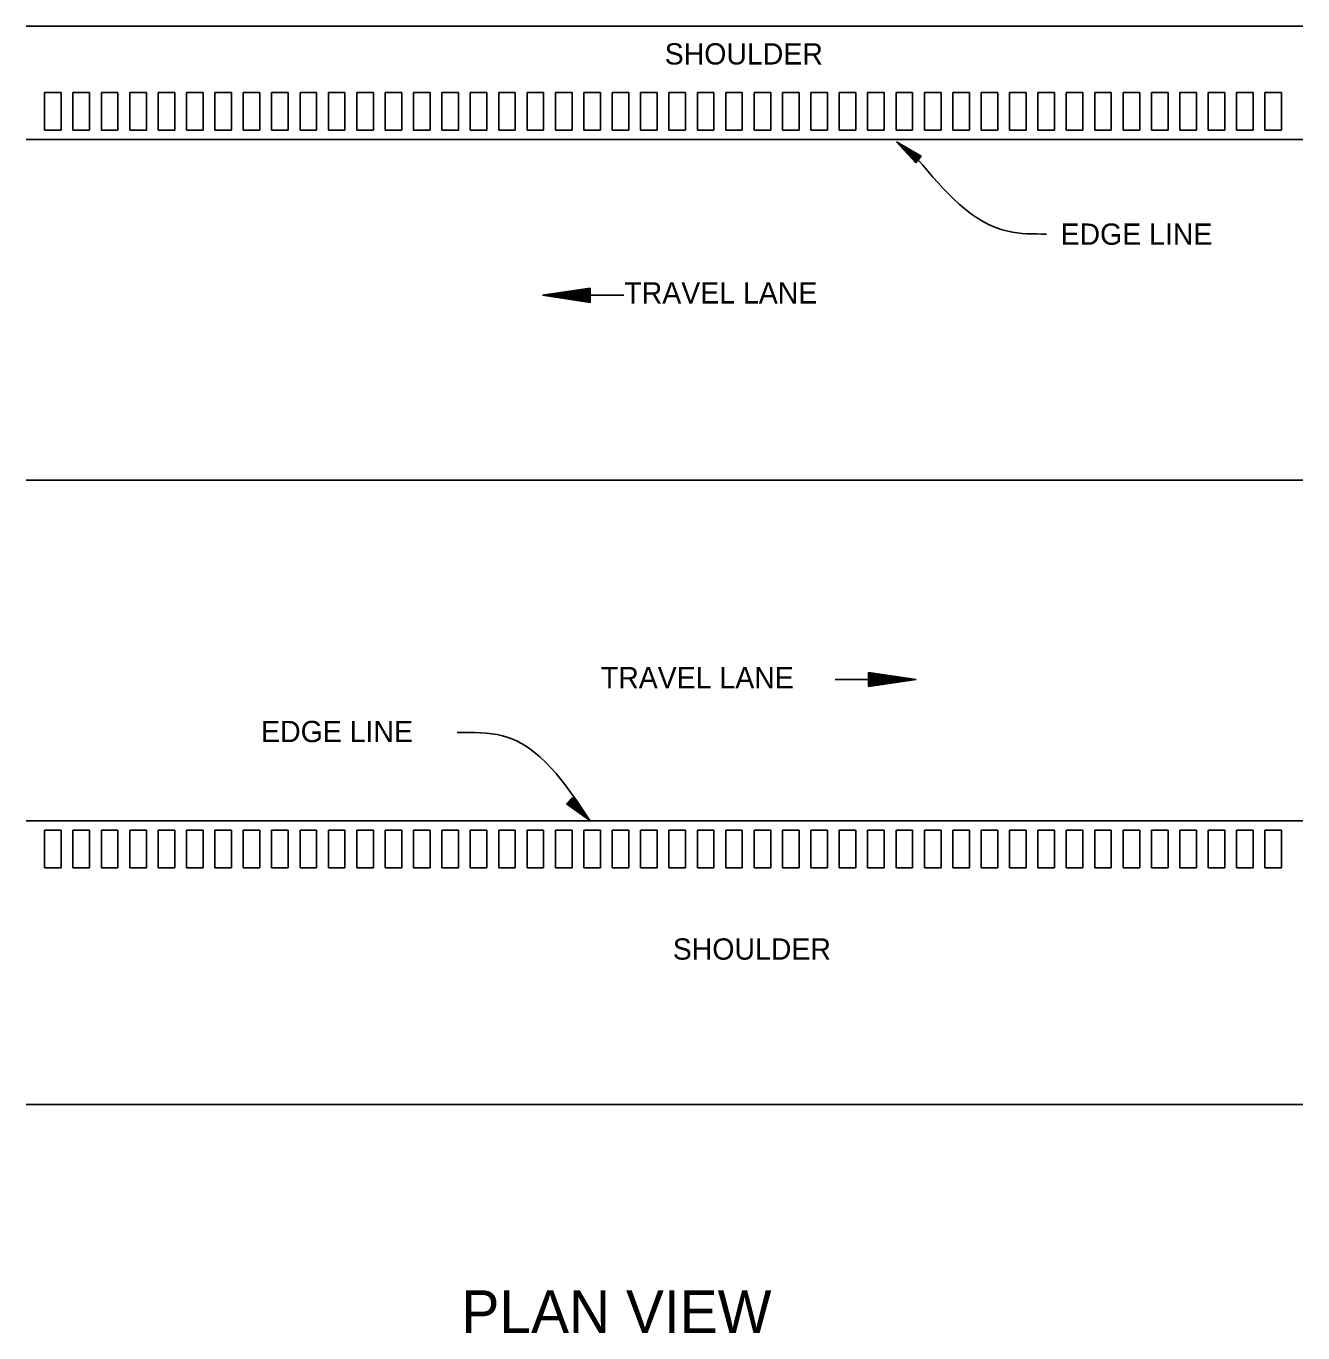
# Model space of a CAD drawing. Extents: x -2842 to 2681, y -2139 to 474.
# Drawn here: x -712.1 to -352.2, y -354.1 to 14.3 of the extents above; entities that cross this region are included whole.
import ezdxf

# ---------------------------------------------------------------- set-up
doc = ezdxf.new("R2010")
doc.units = 0
doc.layers.add('Default', color=7, linetype='Continuous')

msp = doc.modelspace()

# ---------------------------------------------------------------- linework, layer by layer
at = {"layer": 'Default'}
for p, q in [((-712.07, 14.26), (-352.18, 14.26)), ((-706.87, -15.08), (-706.87, -4.44)), ((-706.87, -4.44), (-702.19, -4.44)), ((-702.19, -15.08), (-702.19, -4.44)), ((-698.87, -15.08), (-698.87, -4.44)), ((-698.87, -4.44), (-694.19, -4.44)), ((-694.19, -15.08), (-694.19, -4.44)), ((-690.87, -15.08), (-690.87, -4.44)), ((-690.87, -4.44), (-686.19, -4.44)), ((-686.19, -15.08), (-686.19, -4.44)), ((-682.87, -15.08), (-682.87, -4.44)), ((-682.87, -4.44), (-678.19, -4.44)), ((-678.19, -15.08), (-678.19, -4.44)), ((-674.87, -15.08), (-674.87, -4.44)), ((-674.87, -4.44), (-670.19, -4.44)), ((-670.19, -15.08), (-670.19, -4.44)), ((-666.87, -15.08), (-666.87, -4.44)), ((-666.87, -4.44), (-662.19, -4.44)), ((-662.19, -15.08), (-662.19, -4.44)), ((-658.87, -15.08), (-658.87, -4.44)), ((-658.87, -4.44), (-654.19, -4.44)), ((-654.19, -15.08), (-654.19, -4.44)), ((-650.87, -15.08), (-650.87, -4.44)), ((-650.87, -4.44), (-646.19, -4.44)), ((-646.19, -15.08), (-646.19, -4.44)), ((-642.87, -15.08), (-642.87, -4.44)), ((-642.87, -4.44), (-638.19, -4.44)), ((-638.19, -15.08), (-638.19, -4.44)), ((-634.87, -15.08), (-634.87, -4.44)), ((-634.87, -4.44), (-630.19, -4.44)), ((-630.19, -15.08), (-630.19, -4.44)), ((-626.87, -15.08), (-626.87, -4.44)), ((-626.87, -4.44), (-622.19, -4.44)), ((-622.19, -15.08), (-622.19, -4.44)), ((-618.87, -15.08), (-618.87, -4.44)), ((-618.87, -4.44), (-614.19, -4.44)), ((-614.19, -15.08), (-614.19, -4.44)), ((-610.87, -15.08), (-610.87, -4.44)), ((-610.87, -4.44), (-606.19, -4.44)), ((-606.19, -15.08), (-606.19, -4.44)), ((-602.87, -15.08), (-602.87, -4.44)), ((-602.87, -4.44), (-598.19, -4.44)), ((-598.19, -15.08), (-598.19, -4.44)), ((-594.87, -15.08), (-594.87, -4.44)), ((-594.87, -4.44), (-590.19, -4.44)), ((-590.19, -15.08), (-590.19, -4.44)), ((-586.87, -15.08), (-586.87, -4.44)), ((-586.87, -15.08), (-586.87, -4.44)), ((-586.87, -4.44), (-582.19, -4.44)), ((-582.19, -15.08), (-582.19, -4.44)), ((-578.87, -15.08), (-578.87, -4.44)), ((-578.87, -4.44), (-574.19, -4.44)), ((-574.19, -15.08), (-574.19, -4.44)), ((-570.87, -15.08), (-570.87, -4.44)), ((-570.87, -4.44), (-566.19, -4.44)), ((-566.19, -15.08), (-566.19, -4.44)), ((-562.87, -15.08), (-562.87, -4.44)), ((-562.87, -4.44), (-558.19, -4.44)), ((-558.19, -15.08), (-558.19, -4.44)), ((-554.87, -15.08), (-554.87, -4.44)), ((-554.87, -4.44), (-550.19, -4.44)), ((-550.19, -15.08), (-550.19, -4.44)), ((-546.87, -15.08), (-546.87, -4.44)), ((-546.87, -4.44), (-542.19, -4.44)), ((-542.19, -15.08), (-542.19, -4.44)), ((-538.87, -15.08), (-538.87, -4.44)), ((-538.87, -4.44), (-534.19, -4.44)), ((-534.19, -15.08), (-534.19, -4.44)), ((-530.87, -15.08), (-530.87, -4.44)), ((-530.87, -4.44), (-526.19, -4.44)), ((-526.19, -15.08), (-526.19, -4.44)), ((-522.87, -15.08), (-522.87, -4.44)), ((-522.87, -4.44), (-518.19, -4.44)), ((-518.19, -15.08), (-518.19, -4.44)), ((-514.87, -15.08), (-514.87, -4.44)), ((-514.87, -4.44), (-510.19, -4.44)), ((-510.19, -15.08), (-510.19, -4.44)), ((-506.87, -15.08), (-506.87, -4.44)), ((-506.87, -4.44), (-502.19, -4.44)), ((-502.19, -15.08), (-502.19, -4.44)), ((-498.87, -15.08), (-498.87, -4.44)), ((-498.87, -4.44), (-494.19, -4.44)), ((-494.19, -15.08), (-494.19, -4.44)), ((-490.87, -15.08), (-490.87, -4.44)), ((-490.87, -4.44), (-486.19, -4.44)), ((-486.19, -15.08), (-486.19, -4.44)), ((-482.87, -15.08), (-482.87, -4.44)), ((-482.87, -4.44), (-478.18, -4.44)), ((-478.18, -15.08), (-478.18, -4.44)), ((-474.86, -15.08), (-474.86, -4.44)), ((-474.86, -4.44), (-470.18, -4.44)), ((-470.18, -15.08), (-470.18, -4.44)), ((-466.86, -15.08), (-466.86, -4.44)), ((-466.86, -4.44), (-462.18, -4.44)), ((-462.18, -15.08), (-462.18, -4.44)), ((-458.86, -15.08), (-458.86, -4.44)), ((-458.86, -4.44), (-454.18, -4.44)), ((-454.18, -15.08), (-454.18, -4.44)), ((-450.86, -15.08), (-450.86, -4.44)), ((-450.86, -4.44), (-446.18, -4.44)), ((-446.18, -15.08), (-446.18, -4.44)), ((-442.86, -15.08), (-442.86, -4.44)), ((-442.86, -4.44), (-438.18, -4.44)), ((-438.18, -15.08), (-438.18, -4.44)), ((-434.86, -15.08), (-434.86, -4.44)), ((-434.86, -4.44), (-430.18, -4.44)), ((-430.18, -15.08), (-430.18, -4.44)), ((-426.86, -15.08), (-426.86, -4.44)), ((-426.86, -4.44), (-422.18, -4.44)), ((-422.18, -15.08), (-422.18, -4.44)), ((-418.86, -15.08), (-418.86, -4.44)), ((-418.86, -4.44), (-414.18, -4.44)), ((-414.18, -15.08), (-414.18, -4.44)), ((-410.86, -15.08), (-410.86, -4.44)), ((-410.86, -4.44), (-406.18, -4.44)), ((-406.18, -15.08), (-406.18, -4.44)), ((-402.86, -15.08), (-402.86, -4.44)), ((-402.86, -4.44), (-398.18, -4.44)), ((-398.18, -15.08), (-398.18, -4.44)), ((-394.86, -15.08), (-394.86, -4.44)), ((-394.86, -4.44), (-390.18, -4.44)), ((-390.18, -15.08), (-390.18, -4.44)), ((-386.86, -15.08), (-386.86, -4.44)), ((-386.86, -4.44), (-382.18, -4.44)), ((-382.18, -15.08), (-382.18, -4.44)), ((-378.86, -15.08), (-378.86, -4.44)), ((-378.86, -4.44), (-374.18, -4.44)), ((-374.18, -15.08), (-374.18, -4.44)), ((-370.86, -15.08), (-370.86, -4.44)), ((-370.86, -4.44), (-366.18, -4.44)), ((-366.18, -15.08), (-366.18, -4.44)), ((-362.86, -15.08), (-362.86, -4.44)), ((-362.86, -4.44), (-358.18, -4.44)), ((-358.18, -15.08), (-358.18, -4.44)), ((-712.07, -17.74), (-532.97, -17.74)), ((-702.19, -15.08), (-706.87, -15.08)), ((-694.19, -15.08), (-698.87, -15.08)), ((-686.19, -15.08), (-690.87, -15.08)), ((-678.19, -15.08), (-682.87, -15.08)), ((-670.19, -15.08), (-674.87, -15.08)), ((-662.19, -15.08), (-666.87, -15.08)), ((-654.19, -15.08), (-658.87, -15.08)), ((-646.19, -15.08), (-650.87, -15.08)), ((-638.19, -15.08), (-642.87, -15.08)), ((-630.19, -15.08), (-634.87, -15.08)), ((-622.19, -15.08), (-626.87, -15.08)), ((-614.19, -15.08), (-618.87, -15.08)), ((-606.19, -15.08), (-610.87, -15.08)), ((-598.19, -15.08), (-602.87, -15.08)), ((-590.19, -15.08), (-594.87, -15.08)), ((-582.19, -15.08), (-586.87, -15.08)), ((-574.19, -15.08), (-578.87, -15.08)), ((-566.19, -15.08), (-570.87, -15.08)), ((-558.19, -15.08), (-562.87, -15.08)), ((-550.19, -15.08), (-554.87, -15.08)), ((-542.19, -15.08), (-546.87, -15.08)), ((-534.19, -15.08), (-538.87, -15.08)), ((-352.18, -17.74), (-532.97, -17.74)), ((-526.19, -15.08), (-530.87, -15.08)), ((-518.19, -15.08), (-522.87, -15.08)), ((-510.19, -15.08), (-514.87, -15.08)), ((-502.19, -15.08), (-506.87, -15.08)), ((-494.19, -15.08), (-498.87, -15.08)), ((-486.19, -15.08), (-490.87, -15.08)), ((-478.18, -15.08), (-482.87, -15.08)), ((-470.18, -15.08), (-474.86, -15.08)), ((-462.18, -15.08), (-466.86, -15.08)), ((-461.24, -24.3), (-466.74, -18.36)), ((-459.74, -22.42), (-466.74, -18.36)), ((-454.18, -15.08), (-458.86, -15.08)), ((-446.18, -15.08), (-450.86, -15.08)), ((-438.18, -15.08), (-442.86, -15.08)), ((-430.18, -15.08), (-434.86, -15.08)), ((-422.18, -15.08), (-426.86, -15.08)), ((-414.18, -15.08), (-418.86, -15.08)), ((-406.18, -15.08), (-410.86, -15.08)), ((-398.18, -15.08), (-402.86, -15.08)), ((-390.18, -15.08), (-394.86, -15.08)), ((-382.18, -15.08), (-386.86, -15.08)), ((-374.18, -15.08), (-378.86, -15.08)), ((-366.18, -15.08), (-370.86, -15.08)), ((-358.18, -15.08), (-362.86, -15.08)), ((-461.12, -24.14), (-465.7, -19.2)), ((-459.86, -22.58), (-465.7, -19.2)), ((-460, -22.74), (-464.62, -20.04)), ((-460.98, -23.98), (-464.62, -20.04)), ((-460.86, -23.82), (-463.58, -20.88)), ((-460.12, -22.9), (-463.58, -20.88)), ((-460.26, -23.06), (-462.52, -21.74)), ((-460.74, -23.66), (-462.52, -21.74)), ((-460.38, -23.22), (-461.48, -22.56)), ((-460.62, -23.5), (-461.48, -22.56)), ((-461.24, -24.3), (-459.74, -22.42)), ((-553.05, -59.6), (-566.49, -61.62)), ((-543.61, -61.62), (-566.49, -61.62)), ((-553.05, -63.62), (-566.49, -61.62)), ((-553.05, -59.94), (-564.25, -61.62)), ((-553.05, -63.3), (-564.25, -61.62)), ((-553.05, -60.26), (-561.95, -61.62)), ((-553.05, -62.94), (-561.95, -61.62)), ((-553.05, -60.62), (-559.73, -61.62)), ((-553.05, -62.62), (-559.73, -61.62)), ((-553.05, -60.98), (-557.43, -61.62)), ((-553.05, -62.28), (-557.43, -61.62)), ((-553.05, -61.28), (-555.19, -61.62)), ((-553.05, -61.94), (-555.19, -61.62)), ((-553.05, -59.6), (-553.05, -63.62)), ((-712.07, -113.74), (-352.18, -113.74)), ((-474.58, -167.94), (-461.14, -169.92)), ((-474.58, -171.94), (-474.58, -167.94)), ((-474.58, -168.26), (-463.38, -169.92)), ((-474.58, -168.6), (-465.68, -169.92)), ((-474.58, -168.94), (-467.9, -169.92)), ((-474.58, -169.28), (-470.2, -169.92)), ((-484.03, -169.92), (-461.14, -169.92)), ((-474.58, -169.6), (-472.44, -169.92)), ((-474.58, -171.94), (-461.14, -169.92)), ((-474.58, -170.58), (-470.2, -169.92)), ((-474.58, -171.28), (-465.68, -169.92)), ((-474.58, -171.62), (-463.38, -169.92)), ((-474.58, -170.94), (-467.9, -169.92)), ((-474.58, -170.26), (-472.44, -169.92)), ((-558.07, -203.25), (-559.73, -204.97)), ((-559.73, -204.97), (-553.15, -209.69)), ((-559.59, -204.83), (-554.11, -208.75)), ((-559.45, -204.69), (-555.11, -207.79)), ((-559.31, -204.55), (-556.05, -206.87)), ((-559.17, -204.41), (-557.03, -205.93)), ((-559.03, -204.25), (-557.99, -204.99)), ((-558.77, -203.99), (-557.99, -204.99)), ((-558.63, -203.85), (-557.03, -205.93)), ((-558.49, -203.69), (-556.05, -206.87)), ((-558.35, -203.55), (-555.11, -207.79)), ((-558.21, -203.41), (-554.11, -208.75)), ((-558.07, -203.25), (-553.15, -209.69)), ((-712.07, -209.75), (-532.97, -209.75)), ((-352.18, -209.75), (-532.97, -209.75)), ((-440.06, -209.75), (-352.18, -209.75)), ((-702.19, -212.41), (-706.87, -212.41)), ((-706.87, -212.41), (-706.87, -223.05)), ((-702.19, -212.41), (-702.19, -223.05)), ((-694.19, -212.41), (-698.87, -212.41)), ((-698.87, -212.41), (-698.87, -223.05)), ((-694.19, -212.41), (-694.19, -223.05)), ((-686.19, -212.41), (-690.87, -212.41)), ((-690.87, -212.41), (-690.87, -223.05)), ((-686.19, -212.41), (-686.19, -223.05)), ((-678.19, -212.41), (-682.87, -212.41)), ((-682.87, -212.41), (-682.87, -223.05)), ((-678.19, -212.41), (-678.19, -223.05)), ((-670.19, -212.41), (-674.87, -212.41)), ((-674.87, -212.41), (-674.87, -223.05)), ((-670.19, -212.41), (-670.19, -223.05)), ((-662.19, -212.41), (-666.87, -212.41)), ((-666.87, -212.41), (-666.87, -223.05)), ((-662.19, -212.41), (-662.19, -223.05)), ((-654.19, -212.41), (-658.87, -212.41)), ((-658.87, -212.41), (-658.87, -223.05)), ((-654.19, -212.41), (-654.19, -223.05)), ((-646.19, -212.41), (-650.87, -212.41)), ((-650.87, -212.41), (-650.87, -223.05)), ((-646.19, -212.41), (-646.19, -223.05)), ((-638.19, -212.41), (-642.87, -212.41)), ((-642.87, -212.41), (-642.87, -223.05)), ((-638.19, -212.41), (-638.19, -223.05)), ((-630.19, -212.41), (-634.87, -212.41)), ((-634.87, -212.41), (-634.87, -223.05)), ((-630.19, -212.41), (-630.19, -223.05)), ((-622.19, -212.41), (-626.87, -212.41)), ((-626.87, -212.41), (-626.87, -223.05)), ((-622.19, -212.41), (-622.19, -223.05)), ((-614.19, -212.41), (-618.87, -212.41)), ((-618.87, -212.41), (-618.87, -223.05)), ((-614.19, -212.41), (-614.19, -223.05)), ((-606.19, -212.41), (-610.87, -212.41)), ((-610.87, -212.41), (-610.87, -223.05)), ((-606.19, -212.41), (-606.19, -223.05)), ((-598.19, -212.41), (-602.87, -212.41)), ((-602.87, -212.41), (-602.87, -223.05)), ((-598.19, -212.41), (-598.19, -223.05)), ((-590.19, -212.41), (-594.87, -212.41)), ((-594.87, -212.41), (-594.87, -223.05)), ((-590.19, -212.41), (-590.19, -223.05)), ((-582.19, -212.41), (-586.87, -212.41)), ((-586.87, -212.41), (-586.87, -223.05)), ((-582.19, -212.41), (-582.19, -223.05)), ((-574.19, -212.41), (-578.87, -212.41)), ((-578.87, -212.41), (-578.87, -223.05)), ((-574.19, -212.41), (-574.19, -223.05)), ((-566.19, -212.41), (-570.87, -212.41)), ((-570.87, -212.41), (-570.87, -223.05)), ((-566.19, -212.41), (-566.19, -223.05)), ((-558.19, -212.41), (-562.87, -212.41)), ((-562.87, -212.41), (-562.87, -223.05)), ((-558.19, -212.41), (-558.19, -223.05)), ((-550.19, -212.41), (-554.87, -212.41)), ((-554.87, -212.41), (-554.87, -223.05)), ((-550.19, -212.41), (-550.19, -223.05)), ((-542.19, -212.41), (-546.87, -212.41)), ((-546.87, -212.41), (-546.87, -223.05)), ((-542.19, -212.41), (-542.19, -223.05)), ((-534.19, -212.41), (-538.87, -212.41)), ((-538.87, -212.41), (-538.87, -223.05)), ((-534.19, -212.41), (-534.19, -223.05)), ((-526.19, -212.41), (-530.87, -212.41)), ((-530.87, -212.41), (-530.87, -223.05)), ((-526.19, -212.41), (-526.19, -223.05)), ((-518.19, -212.41), (-522.87, -212.41)), ((-522.87, -212.41), (-522.87, -223.05)), ((-518.19, -212.41), (-518.19, -223.05)), ((-510.19, -212.41), (-514.87, -212.41)), ((-514.87, -212.41), (-514.87, -223.05)), ((-510.19, -212.41), (-510.19, -223.05)), ((-502.19, -212.41), (-506.87, -212.41)), ((-506.87, -212.41), (-506.87, -223.05)), ((-502.19, -212.41), (-502.19, -223.05)), ((-494.19, -212.41), (-498.87, -212.41)), ((-498.87, -212.41), (-498.87, -223.05)), ((-494.19, -212.41), (-494.19, -223.05)), ((-486.19, -212.41), (-490.87, -212.41)), ((-490.87, -212.41), (-490.87, -223.05)), ((-486.19, -212.41), (-486.19, -223.05)), ((-478.18, -212.41), (-482.87, -212.41)), ((-482.87, -212.41), (-482.87, -223.05)), ((-478.18, -212.41), (-478.18, -223.05)), ((-470.18, -212.41), (-474.86, -212.41)), ((-474.86, -212.41), (-474.86, -223.05)), ((-470.18, -212.41), (-470.18, -223.05)), ((-462.18, -212.41), (-466.86, -212.41)), ((-466.86, -212.41), (-466.86, -223.05)), ((-462.18, -212.41), (-462.18, -223.05)), ((-454.18, -212.41), (-458.86, -212.41)), ((-458.86, -212.41), (-458.86, -223.05)), ((-454.18, -212.41), (-454.18, -223.05)), ((-446.18, -212.41), (-450.86, -212.41)), ((-450.86, -212.41), (-450.86, -223.05)), ((-446.18, -212.41), (-446.18, -223.05)), ((-438.18, -212.41), (-442.86, -212.41)), ((-442.86, -212.41), (-442.86, -223.05)), ((-438.18, -212.41), (-438.18, -223.05)), ((-430.18, -212.41), (-434.86, -212.41)), ((-434.86, -212.41), (-434.86, -223.05)), ((-430.18, -212.41), (-430.18, -223.05)), ((-422.18, -212.41), (-426.86, -212.41)), ((-426.86, -212.41), (-426.86, -223.05)), ((-422.18, -212.41), (-422.18, -223.05)), ((-414.18, -212.41), (-418.86, -212.41)), ((-418.86, -212.41), (-418.86, -223.05)), ((-414.18, -212.41), (-414.18, -223.05)), ((-406.18, -212.41), (-410.86, -212.41)), ((-410.86, -212.41), (-410.86, -223.05)), ((-406.18, -212.41), (-406.18, -223.05)), ((-398.18, -212.41), (-402.86, -212.41)), ((-402.86, -212.41), (-402.86, -223.05)), ((-398.18, -212.41), (-398.18, -223.05)), ((-390.18, -212.41), (-394.86, -212.41)), ((-394.86, -212.41), (-394.86, -223.05)), ((-390.18, -212.41), (-390.18, -223.05)), ((-382.18, -212.41), (-386.86, -212.41)), ((-386.86, -212.41), (-386.86, -223.05)), ((-382.18, -212.41), (-382.18, -223.05)), ((-374.18, -212.41), (-378.86, -212.41)), ((-378.86, -212.41), (-378.86, -223.05)), ((-374.18, -212.41), (-374.18, -223.05)), ((-366.18, -212.41), (-370.86, -212.41)), ((-370.86, -212.41), (-370.86, -223.05)), ((-366.18, -212.41), (-366.18, -223.05)), ((-358.18, -212.41), (-362.86, -212.41)), ((-362.86, -212.41), (-362.86, -223.05)), ((-358.18, -212.41), (-358.18, -223.05)), ((-706.87, -223.05), (-702.19, -223.05)), ((-698.87, -223.05), (-694.19, -223.05)), ((-690.87, -223.05), (-686.19, -223.05)), ((-682.87, -223.05), (-678.19, -223.05)), ((-674.87, -223.05), (-670.19, -223.05)), ((-666.87, -223.05), (-662.19, -223.05)), ((-658.87, -223.05), (-654.19, -223.05)), ((-650.87, -223.05), (-646.19, -223.05)), ((-642.87, -223.05), (-638.19, -223.05)), ((-634.87, -223.05), (-630.19, -223.05)), ((-626.87, -223.05), (-622.19, -223.05)), ((-618.87, -223.05), (-614.19, -223.05)), ((-610.87, -223.05), (-606.19, -223.05)), ((-602.87, -223.05), (-598.19, -223.05)), ((-594.87, -223.05), (-590.19, -223.05)), ((-586.87, -223.05), (-582.19, -223.05)), ((-578.87, -223.05), (-574.19, -223.05)), ((-570.87, -223.05), (-566.19, -223.05)), ((-562.87, -223.05), (-558.19, -223.05)), ((-554.87, -223.05), (-550.19, -223.05)), ((-546.87, -223.05), (-542.19, -223.05)), ((-538.87, -223.05), (-534.19, -223.05)), ((-530.87, -223.05), (-526.19, -223.05)), ((-522.87, -223.05), (-518.19, -223.05)), ((-514.87, -223.05), (-510.19, -223.05)), ((-506.87, -223.05), (-502.19, -223.05)), ((-498.87, -223.05), (-494.19, -223.05)), ((-490.87, -223.05), (-486.19, -223.05)), ((-482.87, -223.05), (-478.18, -223.05)), ((-474.86, -223.05), (-470.18, -223.05)), ((-466.86, -223.05), (-462.18, -223.05)), ((-458.86, -223.05), (-454.18, -223.05)), ((-450.86, -223.05), (-446.18, -223.05)), ((-442.86, -223.05), (-438.18, -223.05)), ((-434.86, -223.05), (-430.18, -223.05)), ((-426.86, -223.05), (-422.18, -223.05)), ((-418.86, -223.05), (-414.18, -223.05)), ((-410.86, -223.05), (-406.18, -223.05)), ((-402.86, -223.05), (-398.18, -223.05)), ((-394.86, -223.05), (-390.18, -223.05)), ((-386.86, -223.05), (-382.18, -223.05)), ((-378.86, -223.05), (-374.18, -223.05)), ((-370.86, -223.05), (-366.18, -223.05)), ((-362.86, -223.05), (-358.18, -223.05)), ((-712.07, -289.75), (-352.18, -289.75))]:
    msp.add_line(p, q, dxfattribs=at)
for points in [[(-424.46, -44.36), (-435.3, -43.58), (-460.78, -23.28)], [(-590.55, -184.92), (-577.81, -185.8), (-553.15, -209.69)]]:
    msp.add_spline(points, degree=3, dxfattribs=at)

# ---------------------------------------------------------------- texts
for s, height, p in [('SHOULDER', 6, (-532.07, 3.44)), ('EDGE LINE', 6, (-420.48, -47.38)), ('TRAVEL LANE', 6.0002, (-543.45, -63.94)), ('TRAVEL LANE', 6.0002, (-550.08, -172.42)), ('EDGE LINE', 6, (-645.83, -187.6)), ('SHOULDER', 6, (-529.79, -248.93)), ('PLAN VIEW ', 12, (-589.37, -354.15))]:
    msp.add_text(s, height=height, dxfattribs=at).set_placement(p)

doc.saveas('drawing.dxf')
